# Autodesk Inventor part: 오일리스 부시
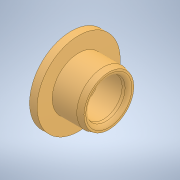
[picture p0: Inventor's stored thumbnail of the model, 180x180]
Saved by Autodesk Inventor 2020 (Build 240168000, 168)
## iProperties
Created: 2024-05
Part Number: 오일리스 부시
Material: 구리, 합금
Document SubType Name: Modeling
Designer: oem
Density: 8.92 g/cm^3
Appearance: 기본값
Author: jhkim
Sending System: Autodesk Inventor 2025
Preprocessor: ST-DEVELOPER v20
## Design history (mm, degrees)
node "오일리스 부시1"
node "솔리드2"
node "솔리드1"
